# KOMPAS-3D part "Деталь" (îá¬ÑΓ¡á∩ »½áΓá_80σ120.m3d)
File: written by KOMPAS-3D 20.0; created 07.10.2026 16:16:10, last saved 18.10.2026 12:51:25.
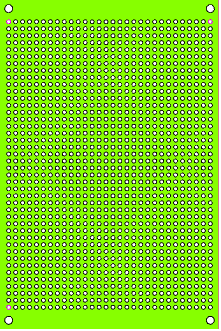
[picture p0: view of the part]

Document properties: Полное имя файла: D:\myProjects\Progect_esp32\box_compas\макетки\Макетная плата_80х120.m3d

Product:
- Part/product: Деталь
    Масса: 0.0865549

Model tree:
1. Эскиз:1
2. Элемент выдавливания:1
     Расстояние 1 = 1.5
3. Эскиз:2  (with: Элемент выдавливания:1)
4. Элемент выдавливания:2
     Расстояние 2 = 1.5
5. Эскиз:3  (with: Элемент выдавливания:1)
6. Элемент выдавливания:3
     Расстояние 2 = 1.5
7. Массив по сетке:1  (with: Элемент выдавливания:3, Эскиз:3, Элемент выдавливания:1)  (1260 pattern instances)
     Шаг 1 = 2.54; Угол раствора = -90; Шаг 2 = 2.54
8. Массив по сетке:2  (with: Элемент выдавливания:2, Эскиз:2, Элемент выдавливания:1)  (4 pattern instances)
     Шаг 1 = 113.66; Угол раствора = 90; Шаг 2 = 73.66; Геометрический массив = 128
9. Эскиз:5  (with: Элемент выдавливания:1, Элемент выдавливания:3)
